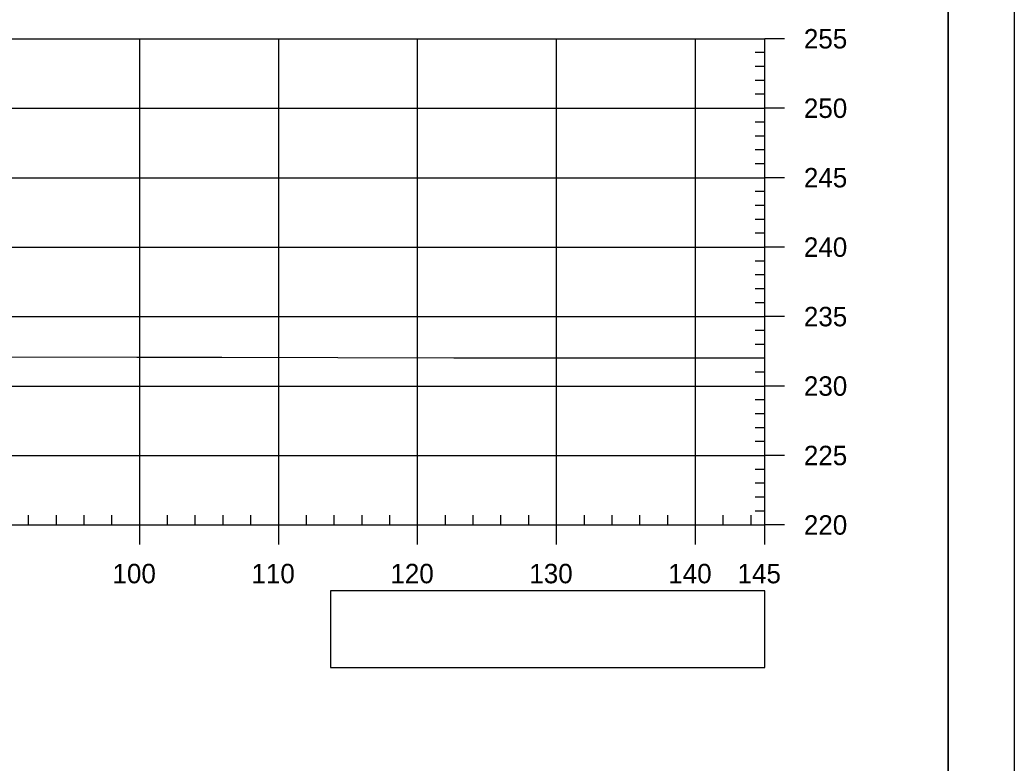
# Model space of a CAD drawing. Extents: x 1386544 to 1388153, y 379785 to 390999.
# Drawn here: x 1387459.9 to 1387531.5, y 384177.9 to 384231.4 of the extents above; entities that cross this region are included whole.
import ezdxf

# ---------------------------------------------------------------- set-up
doc = ezdxf.new("R2010")
doc.units = 0
for name, color, linetype in [('R_Axis', 7, 'Continuous'), ('R_Axis Annot', 7, 'Continuous'), ('R_Border', 7, 'Continuous'), ('R_Exist Surface', 7, 'Continuous'), ('R_Fin Surface', 7, 'Continuous'), ('R_Grid', 7, 'Continuous'), ('R_No Plot', 7, 'Continuous')]:
    doc.layers.add(name, color=color, linetype=linetype)

msp = doc.modelspace()

# ---------------------------------------------------------------- linework, layer by layer
at = {"layer": 'R_Axis'}
for p, q in [((1387513.56, 384195.062), (1387513.56, 384230.062)), ((1387514.96, 384230.062), (1387513.56, 384230.062)), ((1387513.56, 384229.062), (1387512.86, 384229.062)), ((1387513.56, 384228.062), (1387512.86, 384228.062)), ((1387513.56, 384227.062), (1387512.86, 384227.062)), ((1387513.56, 384226.062), (1387512.86, 384226.062)), ((1387514.96, 384225.062), (1387513.56, 384225.062)), ((1387513.56, 384224.062), (1387512.86, 384224.062)), ((1387513.56, 384223.062), (1387512.86, 384223.062)), ((1387513.56, 384222.062), (1387512.86, 384222.062)), ((1387513.56, 384221.062), (1387512.86, 384221.062)), ((1387514.96, 384220.062), (1387513.56, 384220.062)), ((1387513.56, 384219.062), (1387512.86, 384219.062)), ((1387513.56, 384218.062), (1387512.86, 384218.062)), ((1387513.56, 384217.062), (1387512.86, 384217.062)), ((1387513.56, 384216.062), (1387512.86, 384216.062)), ((1387514.96, 384215.062), (1387513.56, 384215.062)), ((1387513.56, 384214.062), (1387512.86, 384214.062)), ((1387513.56, 384213.062), (1387512.86, 384213.062)), ((1387513.56, 384212.062), (1387512.86, 384212.062)), ((1387513.56, 384211.062), (1387512.86, 384211.062)), ((1387514.96, 384210.062), (1387513.56, 384210.062)), ((1387513.56, 384209.062), (1387512.86, 384209.062)), ((1387513.56, 384208.062), (1387512.86, 384208.062)), ((1387513.56, 384207.062), (1387512.86, 384207.062)), ((1387513.56, 384206.062), (1387512.86, 384206.062)), ((1387514.96, 384205.062), (1387513.56, 384205.062)), ((1387513.56, 384204.062), (1387512.86, 384204.062)), ((1387513.56, 384203.062), (1387512.86, 384203.062)), ((1387513.56, 384202.062), (1387512.86, 384202.062)), ((1387513.56, 384201.062), (1387512.86, 384201.062)), ((1387514.96, 384200.062), (1387513.56, 384200.062)), ((1387513.56, 384199.062), (1387512.86, 384199.062)), ((1387513.56, 384198.062), (1387512.86, 384198.062)), ((1387513.56, 384197.062), (1387512.86, 384197.062)), ((1387513.56, 384196.062), (1387512.86, 384196.062)), ((1387460.56, 384195.062), (1387460.56, 384195.762)), ((1387462.56, 384195.062), (1387462.56, 384195.762)), ((1387464.56, 384195.062), (1387464.56, 384195.762)), ((1387466.56, 384195.062), (1387466.56, 384195.762)), ((1387470.56, 384195.062), (1387470.56, 384195.762)), ((1387472.56, 384195.062), (1387472.56, 384195.762)), ((1387474.56, 384195.062), (1387474.56, 384195.762)), ((1387476.56, 384195.062), (1387476.56, 384195.762)), ((1387480.56, 384195.062), (1387480.56, 384195.762)), ((1387482.56, 384195.062), (1387482.56, 384195.762)), ((1387484.56, 384195.062), (1387484.56, 384195.762)), ((1387486.56, 384195.062), (1387486.56, 384195.762)), ((1387490.56, 384195.062), (1387490.56, 384195.762)), ((1387492.56, 384195.062), (1387492.56, 384195.762)), ((1387494.56, 384195.062), (1387494.56, 384195.762)), ((1387496.56, 384195.062), (1387496.56, 384195.762)), ((1387500.56, 384195.062), (1387500.56, 384195.762)), ((1387502.56, 384195.062), (1387502.56, 384195.762)), ((1387504.56, 384195.062), (1387504.56, 384195.762)), ((1387506.56, 384195.062), (1387506.56, 384195.762)), ((1387510.56, 384195.062), (1387510.56, 384195.762)), ((1387512.56, 384195.062), (1387512.56, 384195.762)), ((1387223.56, 384195.062), (1387513.56, 384195.062)), ((1387468.56, 384193.662), (1387468.56, 384195.062)), ((1387478.56, 384193.662), (1387478.56, 384195.062)), ((1387488.56, 384193.662), (1387488.56, 384195.062)), ((1387498.56, 384193.662), (1387498.56, 384195.062)), ((1387508.56, 384193.662), (1387508.56, 384195.062)), ((1387513.56, 384193.662), (1387513.56, 384195.062)), ((1387514.96, 384195.062), (1387513.56, 384195.062))]:
    msp.add_line(p, q, dxfattribs=at)
at = {"layer": 'R_Border'}
msp.add_line((1387526.74, 384060.813), (1387526.74, 384266.273), dxfattribs=at)
at = {"layer": 'R_Exist Surface'}
msp.add_lwpolyline([(1387382.929, 384207.377), (1387390.636, 384207.325), (1387401.045, 384207.236), (1387409.38, 384207.232), (1387423.279, 384207.206), (1387430.821, 384207.203), (1387445.539, 384207.174), (1387452.432, 384207.176), (1387468.356, 384207.138), (1387474.476, 384207.139), (1387491.165, 384207.099), (1387496.856, 384207.091), (1387513.56, 384207.094)], dxfattribs=at)
at = {"layer": 'R_Fin Surface'}
msp.add_lwpolyline([(1387482.301, 384184.799), (1387513.56, 384184.799), (1387513.56, 384190.326), (1387482.301, 384190.326)], close=True, dxfattribs=at)
at = {"layer": 'R_Grid'}
for p, q in [((1387223.56, 384230.062), (1387513.56, 384230.062)), ((1387468.56, 384195.062), (1387468.56, 384230.062)), ((1387478.56, 384195.062), (1387478.56, 384230.062)), ((1387488.56, 384195.062), (1387488.56, 384230.062)), ((1387498.56, 384195.062), (1387498.56, 384230.062)), ((1387508.56, 384195.062), (1387508.56, 384230.062)), ((1387513.56, 384195.062), (1387513.56, 384230.062)), ((1387223.56, 384225.062), (1387513.56, 384225.062)), ((1387223.56, 384220.062), (1387513.56, 384220.062)), ((1387223.56, 384215.062), (1387513.56, 384215.062)), ((1387223.56, 384210.062), (1387513.56, 384210.062)), ((1387223.56, 384205.062), (1387513.56, 384205.062)), ((1387223.56, 384200.062), (1387513.56, 384200.062)), ((1387223.56, 384195.062), (1387513.56, 384195.062))]:
    msp.add_line(p, q, dxfattribs=at)
at = {"layer": 'R_No Plot'}
for points in [[(1387198.153, 384270.168), (1387531.493, 384270.168), (1387531.493, 384056.83), (1387198.153, 384056.83)], [(1387444.48, 384266.273), (1387464.1, 384266.273), (1387464.1, 384256.393), (1387480.212, 384256.393), (1387503.412, 384256.393), (1387503.412, 384232.061), (1387526.74, 384232.061), (1387526.74, 384060.813), (1387210.56, 384060.813), (1387210.56, 384266.273)]]:
    msp.add_lwpolyline(points, close=True, dxfattribs=at)

# ---------------------------------------------------------------- texts
at = {"layer": 'R_Axis Annot'}
for s, p in [('255', (1387516.36, 384229.362)), ('250', (1387516.36, 384224.362)), ('245', (1387516.36, 384219.362)), ('240', (1387516.36, 384214.362)), ('235', (1387516.36, 384209.362)), ('230', (1387516.36, 384204.362)), ('225', (1387516.36, 384199.362)), ('220', (1387516.36, 384194.362)), ('100', (1387466.599, 384190.862)), ('110', (1387476.599, 384190.862)), ('120', (1387486.599, 384190.862)), ('130', (1387496.599, 384190.862)), ('140', (1387506.599, 384190.862)), ('145', (1387511.586, 384190.862))]:
    msp.add_text(s, height=1.4, dxfattribs=at).set_placement(p)

doc.saveas('drawing.dxf')
